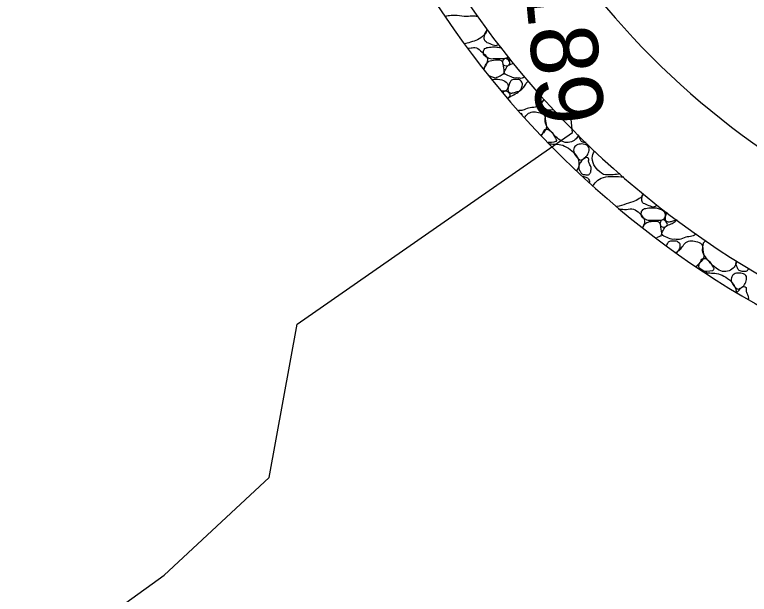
# Model space of a CAD drawing. Extents: x 1385284 to 1385995, y 1975154 to 1975620.
# Drawn here: x 1385530.9 to 1385558.27, y 1975429.75 to 1975451.37 of the extents above; entities that cross this region are included whole.
import ezdxf

# ---------------------------------------------------------------- set-up
doc = ezdxf.new("R2010")
doc.units = 0
for name, color, linetype in [('Default', 7, 'Continuous'), ('DTM_CONTOURS_MINOR', 7, 'Continuous'), ('R_Proposed Const Limits', 7, 'Continuous'), ('R_Proposed Road', 7, 'Continuous')]:
    doc.layers.add(name, color=color, linetype=linetype)

msp = doc.modelspace()

# ---------------------------------------------------------------- linework, layer by layer
at = {"layer": 'Default'}
for radius, start, end in [(35, 144.0867, 263.6071), (34, 144.0867, 263.6071), (20.5, 145.4884, 267.767)]:
    msp.add_arc((1385575.884, 1975470.965), radius, start, end, dxfattribs=at)
for points in [[(1385546.944, 1975451.309), (1385546.961, 1975451.315), (1385547.085, 1975451.348), (1385547.378, 1975451.361), (1385547.737, 1975451.288), (1385548.027, 1975451.35), (1385548.128, 1975451.31), (1385548.152, 1975451.295)], [(1385548.495, 1975450.845), (1385548.492, 1975450.758), (1385548.404, 1975450.586), (1385548.145, 1975450.421), (1385547.895, 1975450.344), (1385547.708, 1975450.289), (1385547.67, 1975450.278)], [(1385548.832, 1975450.206), (1385548.76, 1975450.216), (1385548.615, 1975450.286), (1385548.392, 1975450.356), (1385548.395, 1975450.584), (1385548.448, 1975450.726), (1385548.523, 1975450.793), (1385548.53, 1975450.798)], [(1385547.788, 1975450.123), (1385547.8, 1975450.122), (1385547.895, 1975450.114), (1385548.103, 1975450.178), (1385548.307, 1975449.973), (1385548.559, 1975449.769), (1385548.472, 1975449.479), (1385548.376, 1975449.369), (1385548.367, 1975449.36)], [(1385548.727, 1975449.723), (1385548.671, 1975449.699), (1385548.527, 1975449.757), (1385548.365, 1975449.843), (1385548.354, 1975450.01), (1385548.431, 1975450.142), (1385548.651, 1975450.16), (1385548.858, 1975450.173), (1385549.015, 1975450.139), (1385549.034, 1975450.134)], [(1385548.939, 1975450.259), (1385548.903, 1975450.241), (1385548.867, 1975450.224), (1385548.832, 1975450.206)], [(1385549.278, 1975449.812), (1385549.266, 1975449.775), (1385549.203, 1975449.716), (1385549.007, 1975449.723), (1385548.847, 1975449.717), (1385548.727, 1975449.723)], [(1385549.401, 1975449.651), (1385549.367, 1975449.646), (1385549.292, 1975449.676), (1385549.265, 1975449.75), (1385549.273, 1975449.795), (1385549.277, 1975449.814)], [(1385548.395, 1975449.323), (1385548.396, 1975449.337), (1385548.411, 1975449.425), (1385548.505, 1975449.627), (1385548.721, 1975449.676), (1385549.082, 1975449.706), (1385549.086, 1975449.464), (1385549.167, 1975449.153), (1385548.983, 1975449.076), (1385548.88, 1975449.028), (1385548.832, 1975449.003)], [(1385549.271, 1975449.457), (1385549.233, 1975449.457), (1385549.148, 1975449.455), (1385549.069, 1975449.537), (1385549.077, 1975449.655), (1385549.161, 1975449.757), (1385549.289, 1975449.707), (1385549.392, 1975449.546), (1385549.304, 1975449.487), (1385549.271, 1975449.457)], [(1385549.556, 1975449.003), (1385549.484, 1975448.998), (1385549.349, 1975449.078), (1385549.089, 1975449.168), (1385549.203, 1975449.336), (1385549.273, 1975449.505), (1385549.409, 1975449.52), (1385549.476, 1975449.552)], [(1385548.832, 1975449.003), (1385548.76, 1975449.013), (1385548.669, 1975449.053), (1385548.583, 1975449.09), (1385548.566, 1975449.097)], [(1385549.912, 1975449.046), (1385549.877, 1975449.031), (1385549.77, 1975448.958), (1385549.635, 1975449.023), (1385549.556, 1975449.003)], [(1385548.675, 1975448.955), (1385548.775, 1975448.96), (1385548.986, 1975448.97), (1385549.249, 1975448.864), (1385549.308, 1975448.678), (1385549.213, 1975448.512), (1385549.113, 1975448.521), (1385549.059, 1975448.52), (1385549.046, 1975448.519)], [(1385549.274, 1975448.257), (1385549.343, 1975448.32), (1385549.508, 1975448.366), (1385549.707, 1975448.523), (1385549.886, 1975448.665), (1385549.957, 1975448.825), (1385550.026, 1975448.877), (1385550.048, 1975448.889)], [(1385549.698, 1975448.52), (1385549.651, 1975448.505), (1385549.555, 1975448.482), (1385549.42, 1975448.428), (1385549.293, 1975448.47), (1385549.266, 1975448.577), (1385549.297, 1975448.69), (1385549.34, 1975448.818), (1385549.401, 1975448.942), (1385549.551, 1975448.958), (1385549.723, 1975448.954), (1385549.836, 1975448.827), (1385549.812, 1975448.667), (1385549.751, 1975448.55), (1385549.698, 1975448.52)], [(1385549.095, 1975448.463), (1385549.112, 1975448.488), (1385549.167, 1975448.552), (1385549.289, 1975448.504), (1385549.393, 1975448.344), (1385549.307, 1975448.285), (1385549.274, 1975448.257)], [(1385550.635, 1975448.215), (1385550.602, 1975448.171), (1385550.503, 1975448.07), (1385550.313, 1975447.884), (1385550.037, 1975447.916), (1385549.831, 1975447.777), (1385549.718, 1975447.794), (1385549.671, 1975447.8)], [(1385550.782, 1975447.8), (1385550.734, 1975447.799), (1385550.638, 1975447.872), (1385550.476, 1975447.965), (1385550.564, 1975448.113), (1385550.609, 1975448.188), (1385550.632, 1975448.219)], [(1385549.757, 1975447.701), (1385549.775, 1975447.688), (1385549.79, 1975447.671), (1385549.801, 1975447.651)], [(1385549.905, 1975447.531), (1385549.932, 1975447.567), (1385549.995, 1975447.674), (1385550.192, 1975447.761), (1385550.408, 1975447.735), (1385550.671, 1975447.649), (1385550.663, 1975447.421), (1385550.749, 1975447.11), (1385550.593, 1975446.961), (1385550.515, 1975446.877), (1385550.51, 1975446.872)], [(1385551.464, 1975446.597), (1385551.393, 1975446.594), (1385551.21, 1975446.678), (1385551.014, 1975446.86), (1385550.803, 1975447.084), (1385550.645, 1975447.324), (1385550.677, 1975447.55), (1385550.748, 1975447.793), (1385550.913, 1975447.745), (1385551.016, 1975447.74), (1385551.06, 1975447.737)], [(1385550.977, 1975447.822), (1385550.906, 1975447.803), (1385550.553, 1975447.805), (1385550.824, 1975447.798), (1385550.816, 1975447.8)], [(1385550.533, 1975446.849), (1385550.542, 1975446.872), (1385550.597, 1975446.968), (1385550.632, 1975447.112), (1385550.813, 1975447.086), (1385550.933, 1975446.981), (1385551, 1975446.837), (1385551.184, 1975446.591), (1385550.809, 1975446.606), (1385550.783, 1975446.598)], [(1385551.913, 1975446.878), (1385551.909, 1975446.868), (1385551.863, 1975446.775), (1385551.717, 1975446.641), (1385551.549, 1975446.597), (1385551.464, 1975446.597)], [(1385552.192, 1975446.597), (1385552.191, 1975446.597), (1385552.141, 1975446.598), (1385552.009, 1975446.621), (1385551.971, 1975446.737), (1385551.923, 1975446.819), (1385551.912, 1975446.87), (1385551.91, 1975446.881)], [(1385550.784, 1975446.597), (1385550.793, 1975446.596), (1385550.822, 1975446.595), (1385550.816, 1975446.597)], [(1385550.829, 1975446.552), (1385550.862, 1975446.551), (1385551.003, 1975446.536), (1385551.247, 1975446.543), (1385551.536, 1975446.398), (1385551.793, 1975446.186), (1385551.941, 1975445.927), (1385551.92, 1975445.663), (1385551.855, 1975445.575), (1385551.827, 1975445.547)], [(1385552.042, 1975445.968), (1385552.011, 1975445.894), (1385551.806, 1975446.076), (1385551.704, 1975446.254), (1385551.754, 1975446.474), (1385551.919, 1975446.547), (1385552.146, 1975446.554), (1385552.336, 1975446.429), (1385552.284, 1975446.191), (1385552.171, 1975446.026), (1385552.067, 1975445.979), (1385552.042, 1975445.968)], [(1385552.969, 1975445.398), (1385552.901, 1975445.364), (1385552.678, 1975445.501), (1385552.463, 1975445.747), (1385552.383, 1975446.113), (1385552.495, 1975446.262), (1385552.509, 1975446.279)], [(1385552.368, 1975445.499), (1385552.358, 1975445.474), (1385552.31, 1975445.384), (1385552.187, 1975445.399), (1385552.009, 1975445.418), (1385551.971, 1975445.534), (1385551.897, 1975445.643), (1385551.936, 1975445.807), (1385552.03, 1975445.919), (1385552.107, 1975446.007), (1385552.187, 1975446.063), (1385552.312, 1975446.012), (1385552.269, 1975445.895), (1385552.331, 1975445.769), (1385552.413, 1975445.633), (1385552.349, 1975445.529), (1385552.368, 1975445.499)], [(1385553.45, 1975445.441), (1385553.363, 1975445.418), (1385553.203, 1975445.385), (1385553.041, 1975445.395), (1385552.969, 1975445.398)], [(1385552.049, 1975445.344), (1385552.082, 1975445.342), (1385552.184, 1975445.32), (1385552.3, 1975445.241), (1385552.321, 1975445.138), (1385552.32, 1975445.105)], [(1385552.45, 1975444.99), (1385552.456, 1975445.002), (1385552.556, 1975445.156), (1385552.81, 1975445.317), (1385553.214, 1975445.346), (1385553.458, 1975445.324), (1385553.594, 1975445.315)], [(1385554.326, 1975444.678), (1385554.309, 1975444.642), (1385554.238, 1975444.54), (1385554.014, 1975444.407), (1385553.695, 1975444.316), (1385553.442, 1975444.233), (1385553.334, 1975444.211)], [(1385554.701, 1975444.191), (1385554.629, 1975444.202), (1385554.485, 1975444.271), (1385554.261, 1975444.341), (1385554.262, 1975444.54), (1385554.292, 1975444.642), (1385554.317, 1975444.685)], [(1385553.433, 1975444.123), (1385553.52, 1975444.117), (1385553.689, 1975444.086), (1385553.973, 1975444.164), (1385554.176, 1975443.958), (1385554.406, 1975443.766), (1385554.362, 1975443.531), (1385554.303, 1975443.433)], [(1385554.596, 1975443.708), (1385554.541, 1975443.684), (1385554.396, 1975443.742), (1385554.234, 1975443.829), (1385554.224, 1975443.995), (1385554.301, 1975444.127), (1385554.52, 1975444.145), (1385554.82, 1975444.175), (1385555.118, 1975444.052), (1385555.178, 1975443.866), (1385555.082, 1975443.7), (1385554.876, 1975443.708), (1385554.716, 1975443.702), (1385554.596, 1975443.708)], [(1385554.857, 1975444.267), (1385554.854, 1975444.266), (1385554.802, 1975444.24), (1385554.75, 1975444.216), (1385554.701, 1975444.191)], [(1385555.567, 1975443.708), (1385555.52, 1975443.693), (1385555.424, 1975443.67), (1385555.289, 1975443.617), (1385555.163, 1975443.658), (1385555.135, 1975443.765), (1385555.166, 1975443.879), (1385555.193, 1975443.961), (1385555.207, 1975443.997), (1385555.208, 1975443.998)], [(1385554.296, 1975443.438), (1385554.313, 1975443.482), (1385554.404, 1975443.619), (1385554.59, 1975443.661), (1385554.952, 1975443.691), (1385554.955, 1975443.45), (1385555.037, 1975443.138), (1385554.889, 1975443.079), (1385554.823, 1975443.048), (1385554.81, 1975443.042)], [(1385555.14, 1975443.442), (1385555.102, 1975443.442), (1385555.018, 1975443.44), (1385554.938, 1975443.522), (1385554.946, 1975443.64), (1385555.031, 1975443.742), (1385555.158, 1975443.692), (1385555.261, 1975443.531), (1385555.173, 1975443.472), (1385555.14, 1975443.442)], [(1385555.425, 1975442.988), (1385555.353, 1975442.984), (1385555.218, 1975443.064), (1385554.958, 1975443.153), (1385555.072, 1975443.322), (1385555.151, 1975443.508), (1385555.376, 1975443.553), (1385555.513, 1975443.658), (1385555.572, 1975443.713), (1385555.574, 1975443.715)], [(1385555.576, 1975443.713), (1385555.573, 1975443.712), (1385555.57, 1975443.71), (1385555.567, 1975443.708)], [(1385556.299, 1975443.184), (1385556.274, 1975443.163), (1385556.137, 1975443.077), (1385555.906, 1975443.104), (1385555.669, 1975442.929), (1385555.504, 1975443.009), (1385555.425, 1975442.988)], [(1385555.191, 1975442.749), (1385555.196, 1975442.764), (1385555.217, 1975442.821), (1385555.27, 1975442.927), (1385555.42, 1975442.943), (1385555.592, 1975442.94), (1385555.705, 1975442.812), (1385555.681, 1975442.652), (1385555.62, 1975442.535), (1385555.567, 1975442.505)], [(1385555.546, 1975442.486), (1385555.553, 1975442.492), (1385555.623, 1975442.556), (1385555.755, 1975442.65), (1385555.85, 1975442.856), (1385556.062, 1975442.949), (1385556.277, 1975442.923), (1385556.54, 1975442.837), (1385556.532, 1975442.61), (1385556.619, 1975442.298), (1385556.431, 1975442.118), (1385556.331, 1975442.008), (1385556.299, 1975441.98)], [(1385557.334, 1975441.785), (1385557.262, 1975441.782), (1385557.08, 1975441.866), (1385556.883, 1975442.048), (1385556.673, 1975442.272), (1385556.514, 1975442.513), (1385556.546, 1975442.739), (1385556.573, 1975442.912), (1385556.648, 1975442.938), (1385556.662, 1975442.94)], [(1385555.567, 1975442.505), (1385555.556, 1975442.502), (1385555.544, 1975442.498), (1385555.532, 1975442.495)], [(1385556.651, 1975441.785), (1385556.604, 1975441.784), (1385556.508, 1975441.857), (1385556.345, 1975441.95), (1385556.454, 1975442.135), (1385556.502, 1975442.3), (1385556.683, 1975442.274), (1385556.802, 1975442.17), (1385556.87, 1975442.025), (1385557.057, 1975441.776), (1385556.307, 1975441.794), (1385556.693, 1975441.783), (1385556.685, 1975441.785)], [(1385557.799, 1975442.176), (1385557.801, 1975442.129), (1385557.756, 1975441.986), (1385557.587, 1975441.829), (1385557.418, 1975441.785), (1385557.334, 1975441.785)], [(1385558.237, 1975441.89), (1385558.227, 1975441.865), (1385558.179, 1975441.775), (1385558.056, 1975441.79), (1385557.878, 1975441.809), (1385557.84, 1975441.925), (1385557.767, 1975442.033), (1385557.778, 1975442.133), (1385557.8, 1975442.176)], [(1385558.231, 1975441.92), (1385558.23, 1975441.91), (1385558.232, 1975441.899), (1385558.237, 1975441.89)], [(1385556.661, 1975441.737), (1385556.706, 1975441.746), (1385556.86, 1975441.725), (1385557.116, 1975441.731), (1385557.405, 1975441.586), (1385557.662, 1975441.374), (1385557.762, 1975441.155), (1385557.793, 1975441.028), (1385557.794, 1975441.018)], [(1385557.911, 1975441.156), (1385557.88, 1975441.082), (1385557.675, 1975441.264), (1385557.573, 1975441.442), (1385557.624, 1975441.662), (1385557.788, 1975441.735), (1385558.015, 1975441.742), (1385558.205, 1975441.617), (1385558.154, 1975441.379), (1385558.041, 1975441.214), (1385557.937, 1975441.167), (1385557.911, 1975441.156)], [(1385557.819, 1975441.004), (1385557.846, 1975441.046), (1385557.905, 1975441.114), (1385557.976, 1975441.196), (1385558.056, 1975441.251), (1385558.181, 1975441.2), (1385558.138, 1975441.083), (1385558.2, 1975440.957), (1385558.244, 1975440.837), (1385558.239, 1975440.773), (1385558.237, 1975440.761)]]:
    msp.add_open_spline(points, degree=3, dxfattribs=at)
at = {"layer": 'DTM_CONTOURS_MINOR'}
msp.add_lwpolyline([(1385478.256, 1975380.205), (1385489.001, 1975390.714), (1385497.875, 1975398.227), (1385502.316, 1975402.528), (1385511.581, 1975410.358), (1385515.659, 1975414.263), (1385525.247, 1975422.378), (1385536.47, 1975430.463), (1385540.382, 1975434.109), (1385541.426, 1975439.822), (1385551.684, 1975446.971), (1385551.625, 1975447.585)], dxfattribs=at)
at = {"layer": 'R_Proposed Const Limits'}
msp.add_arc((1385575.884, 1975470.965), 30, 145.4884, 267.767, dxfattribs=at)
at = {"layer": 'R_Proposed Road'}
msp.add_arc((1385514.357, 1974795.066), 683.494, 77.498258, 106.910819, dxfattribs=at)

# ---------------------------------------------------------------- texts
at = {"layer": 'Default'}
msp.add_text('189', height=2.5, rotation=275.4519, dxfattribs=at).set_placement((1385549.88, 1975452.718))

doc.saveas('drawing.dxf')
